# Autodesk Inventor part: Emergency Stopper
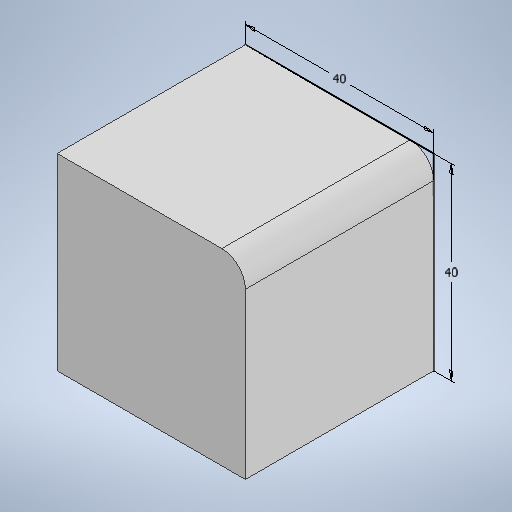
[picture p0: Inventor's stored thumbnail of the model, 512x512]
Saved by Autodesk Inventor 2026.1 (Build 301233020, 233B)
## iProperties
Created: 2026-11
Part Number: Emergency Stopper
Material: Generic
Document SubType Name: Modeling
Designer: hp
Density: 1 g/cm^3
Appearance: Default
Author: hp
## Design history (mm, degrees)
sketch "Sketch1"
  geometry: L1 (0, 0)-(40, 0); L2 (40, 0)-(40, 40); L3 (40, 40)-(0, 40); L4 (0, 40)-(0, 0)
  constraints: 8 end point, 2 parallel, 1 horizontal, 1 perpendicular
  dimensions: "d6" = 40 distance of L3.end L2.end; "d7" = 40 distance of L2.end L1.end
extrude "Extrusion2" new body sketch "Sketch1" distance "d8" = 40; taper "d9" = 0 deg
fillet "Fillet1" dims "d10" = 5
body "Solid2"
